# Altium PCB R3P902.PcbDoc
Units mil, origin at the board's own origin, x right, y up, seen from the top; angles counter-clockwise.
Board outline 3937.01 x 3937.01 mil, 2 copper layers (Top Layer, Bottom Layer); 36 components, 12 nets, 76 pads, 4 vias.
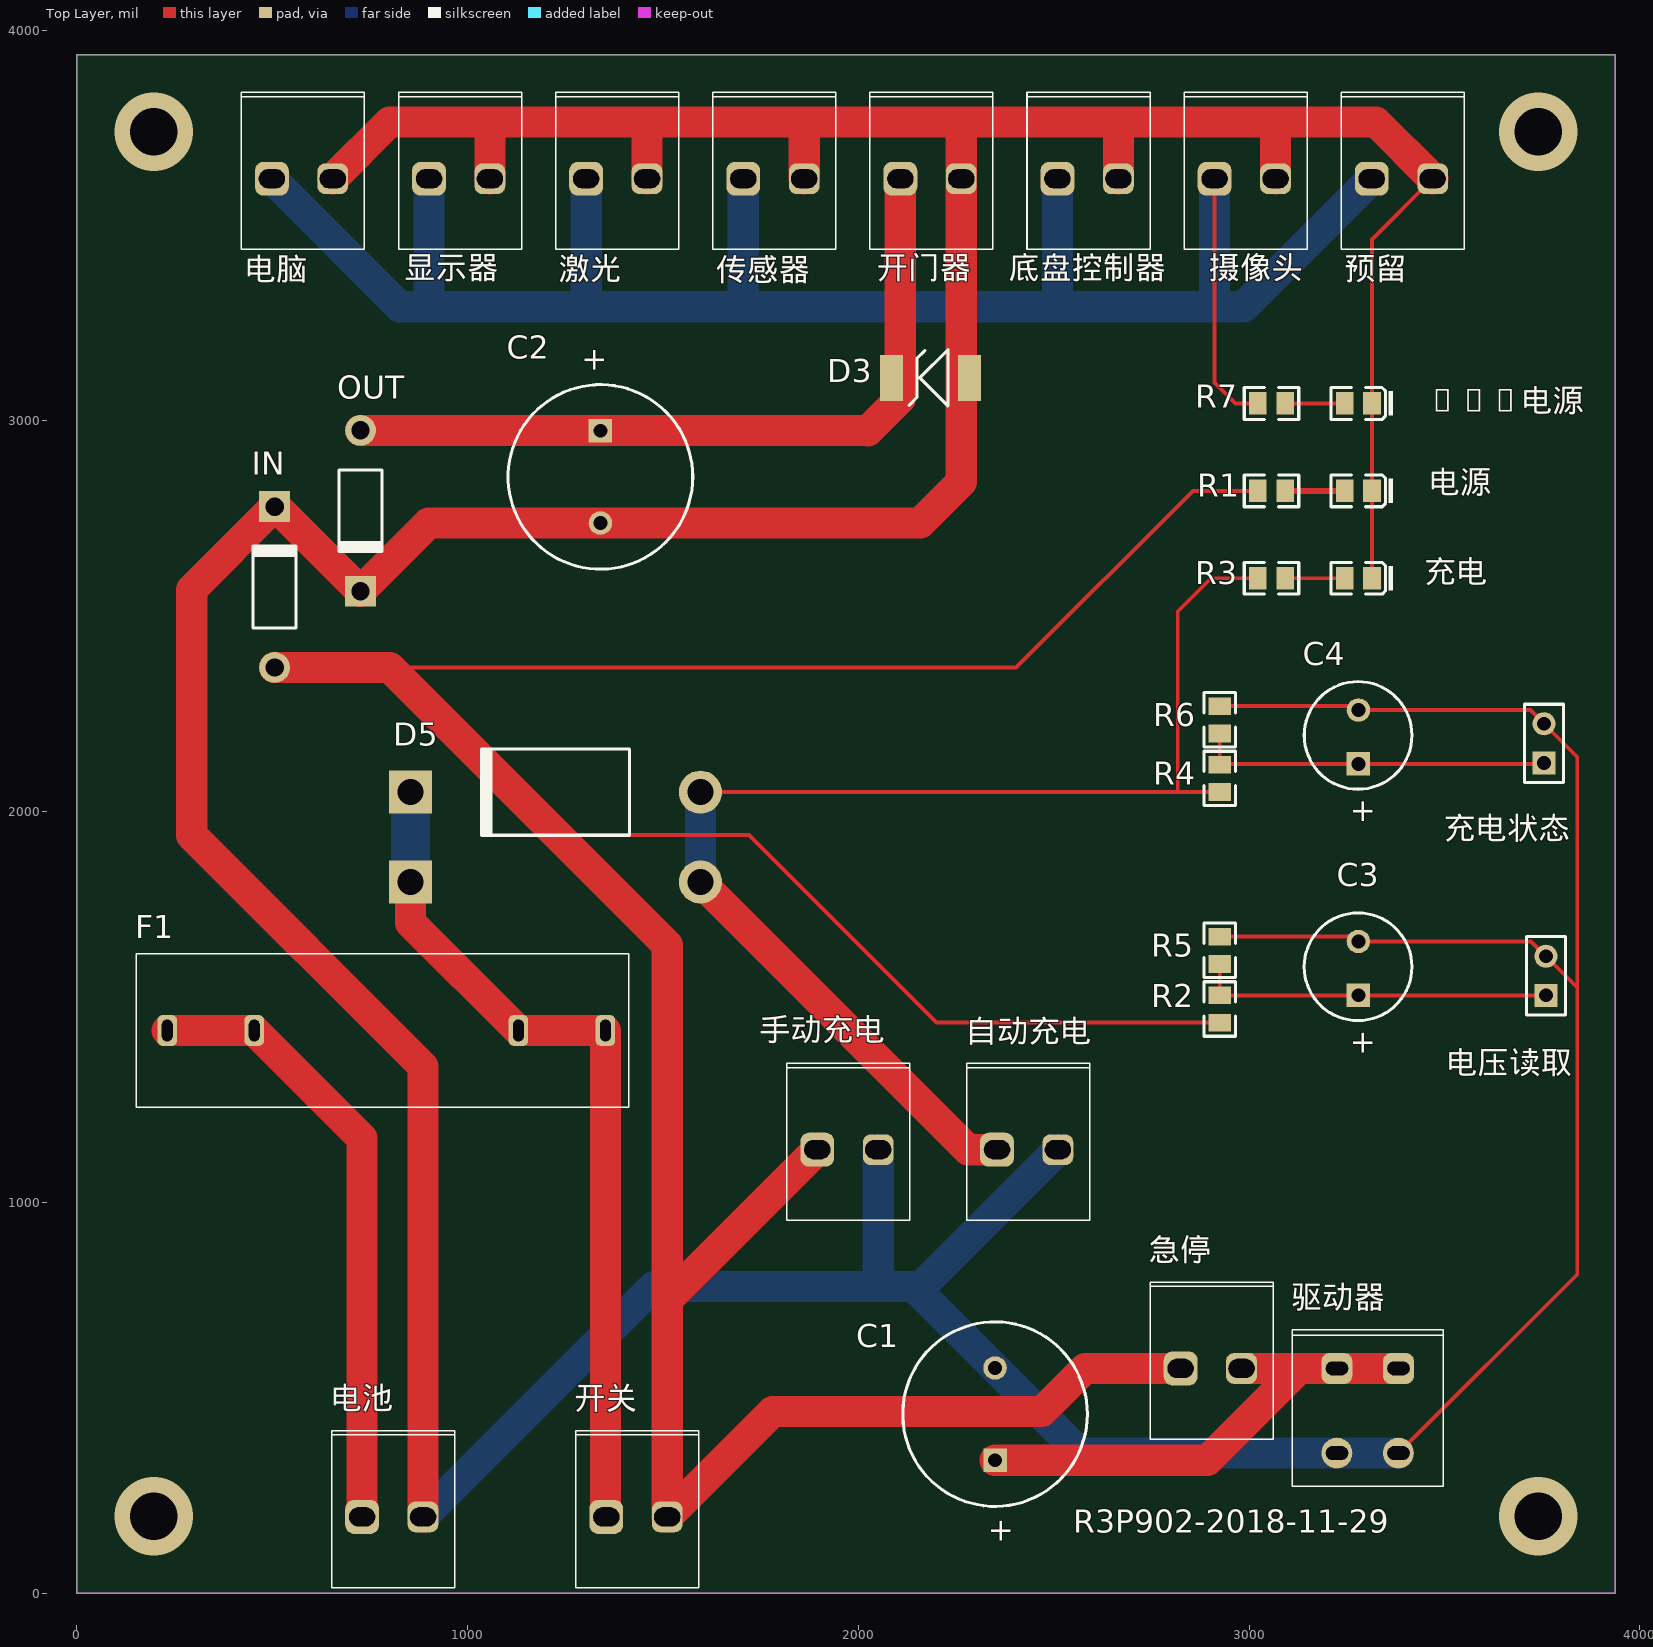
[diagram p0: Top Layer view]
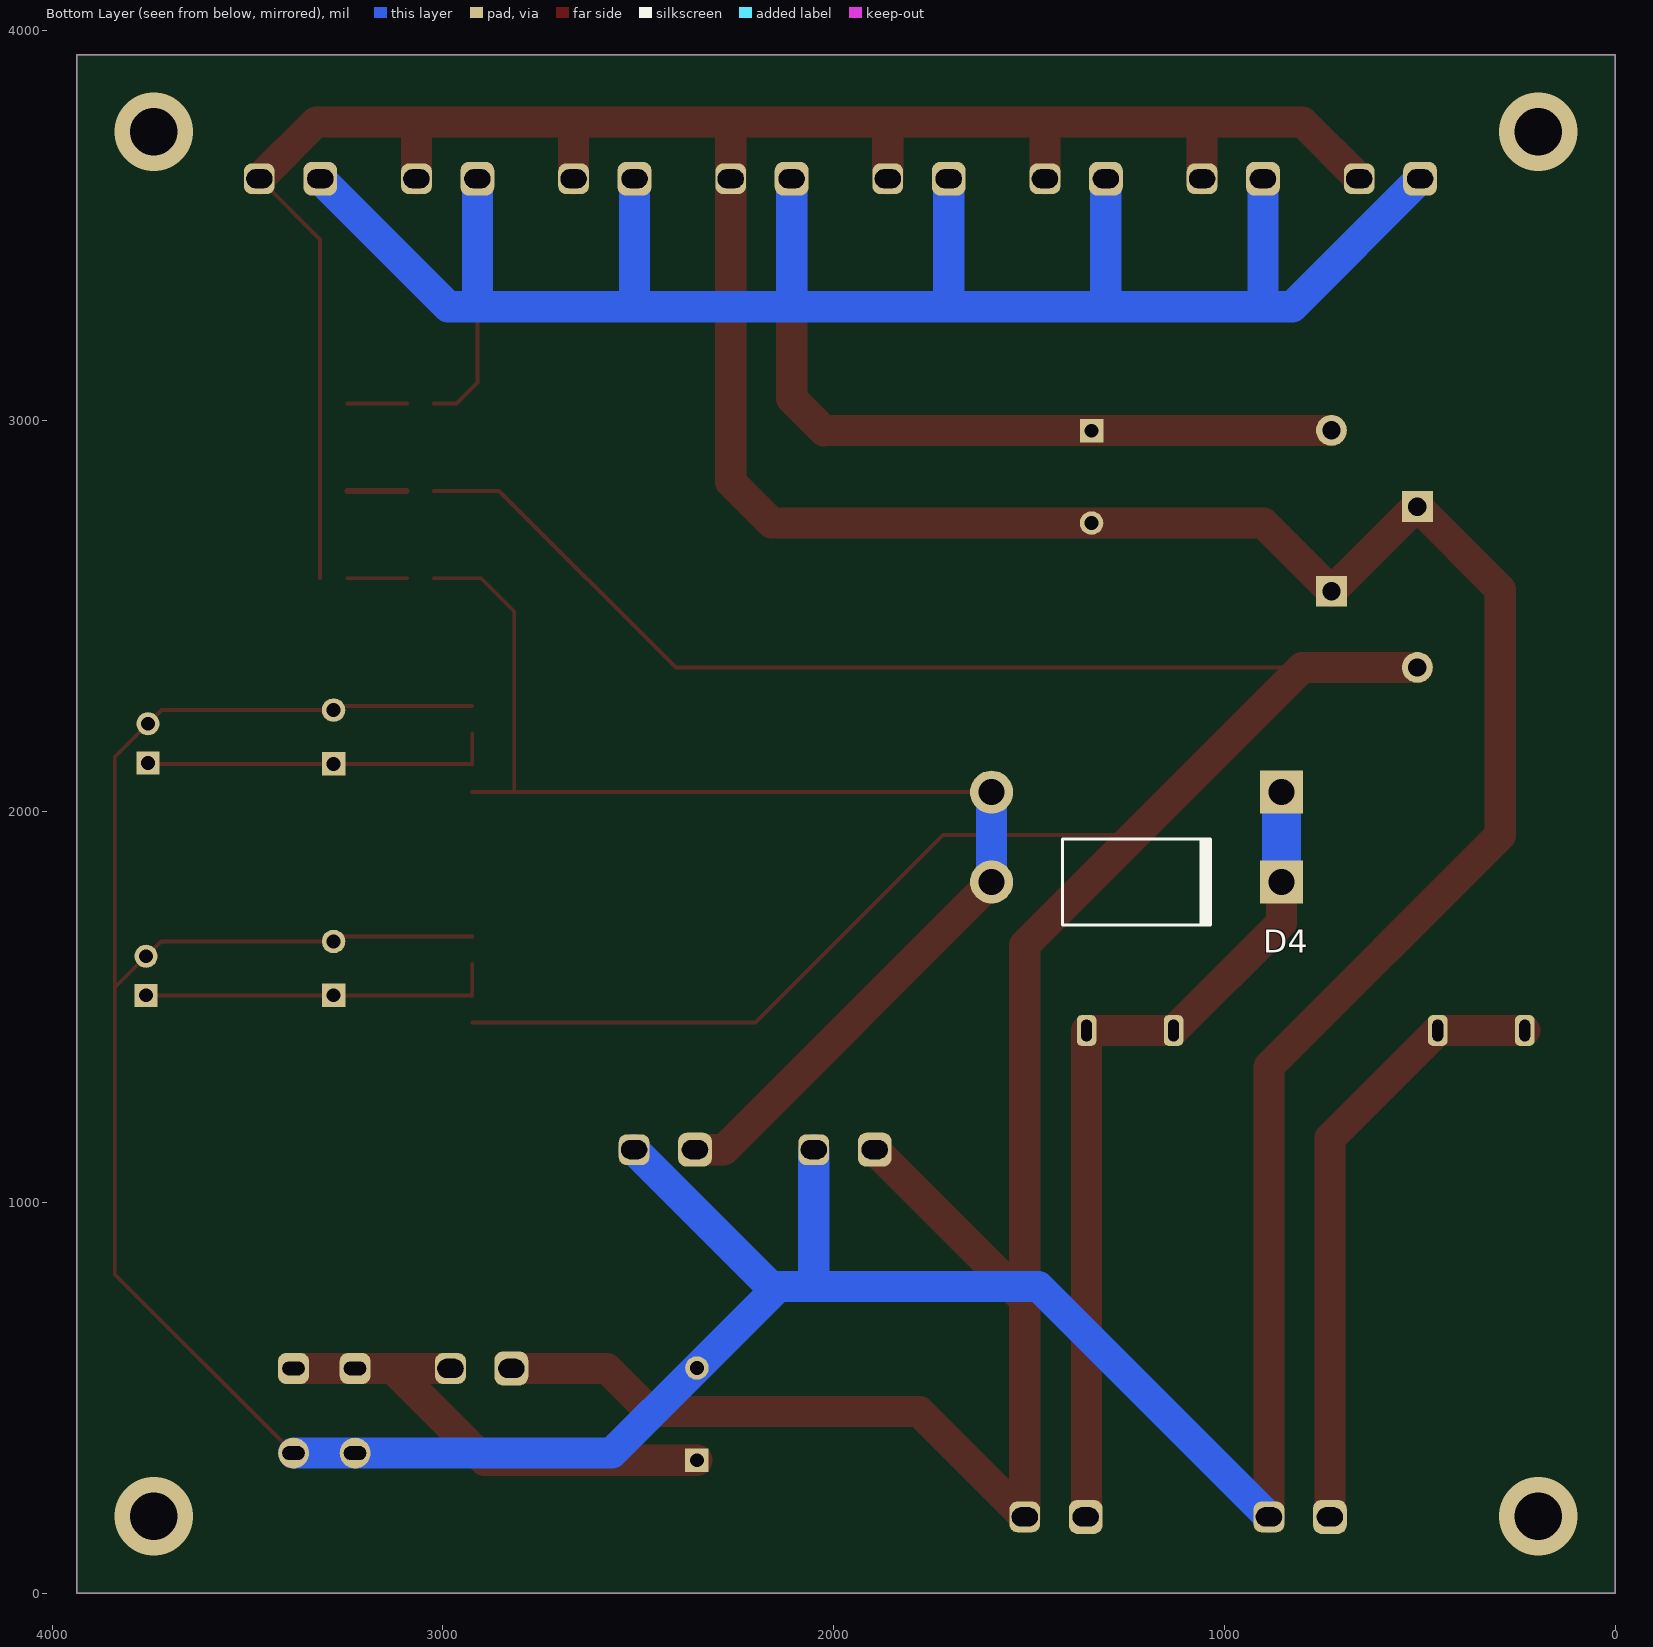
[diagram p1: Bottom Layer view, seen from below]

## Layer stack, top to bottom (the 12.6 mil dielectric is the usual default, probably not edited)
Top Solder: solder mask 0.4, Solder Resist, Dk 3.5
Top Layer: signal copper 1.4
Dielectric 1: dielectric 12.6, FR-4, Dk 4.8
Bottom Layer: signal copper 1.4
Bottom Solder: solder mask 0.4, Solder Resist, Dk 3.5

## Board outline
0,0 0,3937.01 3937.01,3937.01 3937.01,0

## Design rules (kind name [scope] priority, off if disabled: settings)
Clearance [All] p1: gap=8 ignorepadtopadclearanceinfootprint=FALSE
PlaneClearance [All] p1: clearance=50
PolygonConnect [All] p1: connectstyle=Relief reliefconductorwidth=12 reliefentries=4 polygonreliefangle="90 Angle" airgapwidth=10
RoutingVias [All] p1: holewidth=28 width=50 viastyle="Through Hole" minholewidth=28 minwidth=50 maxholewidth=28 maxwidth=50
SolderMaskExpansion [All] p1: expansion=4
Width [All] p1: maxlimit=200 minlimit=10 preferedwidth=50
29 further rules are at their usual default settings.

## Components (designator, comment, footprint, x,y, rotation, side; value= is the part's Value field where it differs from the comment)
12V电源 "红灯 0805" LC-0805_LED_S1 3279.92,3045 r180 top
C1 "Cap" Cap-DIP-7.5 2350,340 r270 top
C2 "Cap" Cap-DIP-7.5 1340,2975 r90 top
C3 "Cap" CAP-DIP-3.5 3280,1530.04 r270 top
C4 "Cap" CAP-DIP-3.5 3280.08,2122.24 r270 top
D3 "SMBJ12A" SMBJ 2190,3110 r180 top
D4 "Diode 1N5408" DO-201AD 1225,1820 r180 bottom
D5 "Diode 1N5408" DO-201AD 1225,2050 r180 top
F1 "Fuse" Fuse 152.44,1243.15 r0 top
IN "Diode 11DQ03" DO-204AL 505.91,2575 r90 top
OUT "Diode 11DQ03" DO-204AL 725.91,2770 r270 top
R1 "20KΩ (2002) ±1%" LC-0805_R 3057.57,2821.25 r0 top
R2 "50KΩ (5002) ±1%" LC-0805_R 2925,1495 r270 top
R3 "20KΩ (2002) ±1%" LC-0805_R 3057.57,2597.5 r0 top
R4 "50KΩ (5002) ±1%" LC-0805_R 2925,2085.04 r270 top
R5 "10KΩ (1002) ±1%" LC-0805_R 2925,1645.04 r270 top
R6 "10KΩ (1002) ±1%" LC-0805_R 2925,2235 r270 top
R7 "10KΩ (1002) ±1%" LC-0805_R 3057.57,3045 r180 top
传感器 "Header 2" "VH-2A - Circle Hole" 1705.52,3620 r0 top
充电 "红灯 0805" LC-0805_LED_S1 3279.92,2597.5 r180 top
充电状态 "Header 2" HDR1X2 3755.08,2125.04 r90 top
底盘控制器 "Header 2" "VH-2A - Circle Hole" 2509.81,3620 r0 top
开关 "Header 2" "VH-2A - Circle Hole" 1355,195 r0 top
开门器 "Header 2" "VH-2A - Circle Hole" 2107.67,3620 r0 top
急停 "Header 2" "VH-2A - Circle Hole" 2825,575 r0 top
手动充电 "Header 2" "VH-2A - Circle Hole" 1895,1135 r0 top
摄像头 "Header 2" "VH-2A - Circle Hole" 2911.95,3620 r0 top
显示器 "Header 2" "VH-2A - Circle Hole" 901.24,3620 r0 top
激光 "Header 2" "VH-2A - Circle Hole" 1303.38,3620 r0 top
电压读取 "Header 2" HDR1X2 3760,1530.04 r90 top
电池 "Header 2" "VH-2A - Circle Hole" 730,195 r0 top
电源 "红灯 0805" LC-0805_LED_S1 3279.92,2821.25 r180 top
电脑 "Header 2" "VH-2A - Circle Hole" 499.09,3620 r0 top
自动充电 "Header 2" "VH-2A - Circle Hole" 2355,1135 r0 top
预留 "Header 2" "VH-2A - Circle Hole" 3314.09,3620 r0 top
驱动器 "插座" "HEADER 2X2" 3110.83,273.82 r0 top

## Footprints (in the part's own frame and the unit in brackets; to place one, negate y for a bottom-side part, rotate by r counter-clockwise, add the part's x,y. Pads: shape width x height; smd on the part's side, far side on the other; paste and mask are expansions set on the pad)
CAP-DIP-3.5 [mil]
  rect 60x60 hole 35.43: 1(0,0)
  round 60 hole 35.43: 2(-137.8,0)
  silkscreen extent -211,-139 65,137
Cap-DIP-7.5 [mil] "100mil_DIP"
  rect 60x60 hole 35.43: 1(0,0)
  round 60 hole 35.43: 2(-236.22,0)
  silkscreen extent -354,-236 118,236
DO-201AD [mm] "Diode, Axial; Body 9.5 x 5.6 mm (LxDia. max), Lead Dia. 1.32 mm (max)"
  round 2.8 hole 1.7: 1(-9.42,0)
  rect 2.8x2.8 hole 1.7: 2(9.42,0)
  silkscreen extent -4.8,-2.8 4.9,2.8
DO-204AL [mm] "Diode, Axial; Body 5.2 x 2.7 mm (LxDia. max), Lead Dia. 0.86 mm (max)"
  round 2 hole 1.2: 1(-5.23,0)
  rect 2x2 hole 1.2: 2(5.23,0)
  silkscreen extent -2.65,-1.4 2.75,1.4
Fuse [mm] "直插保险丝夹"
  rrect50% 1.27x2 hole 1.4 slot 0.7 at 0 deg: 1(2,5) 1(7.66,5) 2(24.83,5) 2(30.49,5)
  silkscreen extent 0,0 32,10
HDR1X2 [mm] "Connector; Header; 2 Position"
  rect 1.5x1.5 hole 0.9: 1(0,0)
  round 1.5 hole 0.9: 2(2.54,0)
  silkscreen extent -1.27,-1.27 3.81,1.27
"HEADER 2X2" [mm] "Header 2X2"
  rrect50% 2x2 hole 0.9 slot 1.45 at 0 deg: 1(2.9,7.65) 3(6.9,7.65)
  round 2 hole 0.9 slot 1.45 at 0 deg: 2(2.9,2.15) 4(6.9,2.15)
  silkscreen extent 0,0 9.8,10.16
LC-0805_LED_S1 [mm]
  rect 1.16x1.47 smd: A(0.89,0) K(-0.89,0)
  silkscreen extent -2.25,-1.04 1.77,1.03, body extent -1.01,-0.62 1.01,0.62, height 1.1
LC-0805_R [mm]
  rect 1.16x1.47 smd: 1(-0.89,0) 2(0.89,0)
  silkscreen extent -1.77,-1.04 1.77,1.03, body extent -1,-0.62 1,0.63, height 0.49
SMBJ [mm]
  rect 1.5x3 smd: 1(-2.413,0) 2(2.667,0)
  silkscreen extent -1.02,-1.85 1.52,1.83
"VH-2A - Circle Hole" [mm] "Header 2 use for Power"
  rrect50% 2.2x2.2 hole 1.24 slot 1.7 at 0 deg: 1(0,0)
  rrect50% 2x2 hole 1.24 slot 1.7 at 0 deg: 2(3.96,0)
  silkscreen extent -1.98,-4.6 6.02,5.61

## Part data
12V电源 充电 电源: library part "0805 红灯", "发光二极管", Package=0805, SuppliersPartNumber=C2295
C1 C2 C3 C4: library part Cap_DIP, "Cap_DIP"
D3: library part SMBJ, "TVS"
D4 D5: "3 Amp Medium Power Silicon Rectifier Diode"
F1: library part FUSE, "Fuse-DIP"
IN OUT: "Schottky Rectifier"
R1 R3: library part "0805 20KΩ (2002) 1%", "贴片电阻", Package=0805, SuppliersPartNumber=C4328
R2 R4 R5 R6 R7: library part "0805 10KΩ (1002) 1%", "贴片电阻", Package=0805, SuppliersPartNumber=C17414
传感器 底盘控制器 开关 开门器 急停 手动充电 摄像头 显示器 激光 电池 电脑 自动充电 预留: "贴片2p座"
充电状态 电压读取: "Header, 2-Pin"
驱动器: library part HEADER_2X2

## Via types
v1: diameter 200.79, hole 122.05, Top Layer to Bottom Layer, 4 vias

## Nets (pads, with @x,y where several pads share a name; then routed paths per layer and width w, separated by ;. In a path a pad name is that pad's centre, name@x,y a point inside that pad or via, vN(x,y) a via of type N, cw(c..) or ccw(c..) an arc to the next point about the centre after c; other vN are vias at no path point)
+12: C2.1 D3.2 OUT.1 R7.2 传感器.1 底盘控制器.1 开门器.1 摄像头.1 显示器.1 激光.1 电脑.1 预留.1 | length 7691.5
  Top Layer w10: 摄像头.1 2911.95,3098.05 2965,3045 R7.2
  Top Layer w80: OUT.1 2024.09,2975.91 2025,2975 2107.67,3057.67 开门器.1
  Bottom Layer w80: 电脑.1 826.43,3292.67 900,3292.67 ; 显示器.1 901.24,3293.9 900,3292.67 ; 激光.1 1303.38,3299.29 1310,3292.67 ; 传感器.1 1705.52,3297.14 1710,3292.67 ; 开门器.1 2107.67,3292.67 ; 底盘控制器.1 2509.81,3297.86 2515,3292.67 ; 摄像头.1 2911.95,3294.62 2910,3292.67 ; 预留.1 2986.76,3292.67 2910,3292.67 ; 900,3292.67 1310,3292.67 ; 1310,3292.67 1710,3292.67 ; 1710,3292.67 2107.67,3292.67 ; 2107.67,3292.67 2515,3292.67 ; 2515,3292.67 2910,3292.67
+24_INCONTROL: D4.1 D5.1 R3.1 R4.2 自动充电.1 | length 3305.8
  Top Layer w10: D5.1 2815,2050 ; R4.2 2815,2050 ; R3.1 2902.5,2597.5 2817.5,2512.5 2817.5,2052.5 2815,2050
  Top Layer w80: D4.1 2280.87,1135 自动充电.1
  Bottom Layer w80: D4.1 D5.1
+Motor: C1.1 急停.2 驱动器.1 驱动器.3 | length 1277.7
  Top Layer w80: C1.1 2893.78,340 3128.78,575 ; 急停.2 3128.78,575 ; 驱动器.3 驱动器.1 3128.78,575
Battery: D4.2 D5.2 F1.2 开关.1 | length 2193
  Top Layer w80: D4.2 854.13,1715.87 1130,1440 1352.83,1440 1352.83,197.17 开关.1
  Bottom Layer w100: D4.2 D5.2
Battery_IN: IN.1 R1.1 R2.2 开关.2 急停.1 手动充电.1 | length 9070.6
  Top Layer w10: 800.91,2369.09 2404.09,2369.09 2856.25,2821.25 R1.1 ; 1240,1940 1720,1940 2200.04,1459.96 R2.2
  Top Layer w80: IN.1 800.91,2369.09 1510.91,1659.09 1510.91,750.91 ; 手动充电.1 1510.91,750.91 ; 急停.1 2580,575 2470,465 1780.91,465 开关.2 1510.91,750.91
Battery_V: C3.1 R2.1 R5.2 电压读取.1 | length 915
  Top Layer w10: R5.2 R2.1 C3.1 电压读取.1
GND: 12V电源.K C1.2 C2.2 C3.2 C4.2 D3.1 IN.2 OUT.2 R5.1 R6.1 传感器.2 充电.K 充电状态.2 底盘控制器.2 开门器.2 手动充电.2 摄像头.2 显示器.2 激光.2 电压读取.2 电池.2 电源.K 电脑.2 自动充电.2 预留.2 驱动器.2 驱动器.4 | length 18256.9
  Top Layer w10: R5.1 3267.76,1680.08 C3.2 3722.2,1667.83 电压读取.2 3840,1550.04 ; R6.1 3270.08,2270.04 C4.2 3720.08,2260.04 充电状态.2 3840,2140.12 3840,1550.04 ; 充电.K 电源.K 12V电源.K 3314.96,3464.96 预留.2 ; 驱动器.4 3840,815.98 3840,1550.04
  Top Layer w80: 电脑.2 800,3765 1050,3765 ; 电池.2 885.91,1347.87 293.78,1940 293.78,2568.78 IN.2 509.09,2780.91 OUT.2 900.59,2738.78 C2.2 2158.78,2738.78 2263.57,2843.57 开门器.2 2263.57,3765 ; 显示器.2 1057.14,3757.86 1050,3765 ; 激光.2 1459.29,3754.29 1470,3765 ; 传感器.2 1861.43,3758.57 1855,3765 ; 底盘控制器.2 2665.71,3755.71 2675,3765 ; 摄像头.2 3067.86,3762.86 3070,3765 ; 预留.2 3325,3765 3070,3765 ; 1050,3765 1470,3765 ; 1470,3765 1855,3765 ; 1855,3765 2263.57,3765 ; 2263.57,3765 2675,3765 ; 2675,3765 3070,3765
  Bottom Layer w80: 电池.2 1475.91,785 2050,785 ; 手动充电.2 2050.91,785.91 2050,785 ; 自动充电.2 2160.91,785 2141.22,785 ; 驱动器.4 驱动器.2 2567.76,358.46 C1.2 2141.22,785 ; 2050,785 2141.22,785
In_Charge: C4.1 R4.1 R6.2 充电状态.1 | length 912
  Top Layer w10: R6.2 R4.1 2927.17,2122.24 C4.1 3752.28,2122.24 充电状态.1
Net12V电源_A: 12V电源.A R7.1 | length 152.3
  Top Layer w10: R7.1 12V电源.A
NetF1_1: F1.1 电池.1 | length 1582.2
  Top Layer w80: F1.1@231.18,1440 454.02,1440 730,1164.02 电池.1
NetR1_2: R1.2 电源.A | length 152.3
  Top Layer w15: R1.2@3092.61,2821.25 电源.A
NetR3_2: R3.2 充电.A | length 152.3
  Top Layer w10: R3.2 充电.A
copper on no net:
  other v1: 196.85,196.85 3740.16,196.85 196.85,3740.16 3740.16,3740.16

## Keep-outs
Keep-Out Layer:
  the board outline again, w3.94

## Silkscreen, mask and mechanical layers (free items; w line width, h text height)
Top Overlay:
  text "R3P902-2018-11-29" at 2550,135 h100

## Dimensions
0,0 to 3937.01,0 on Top Overlay
0,3937.01 to 0,0 on Top Overlay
